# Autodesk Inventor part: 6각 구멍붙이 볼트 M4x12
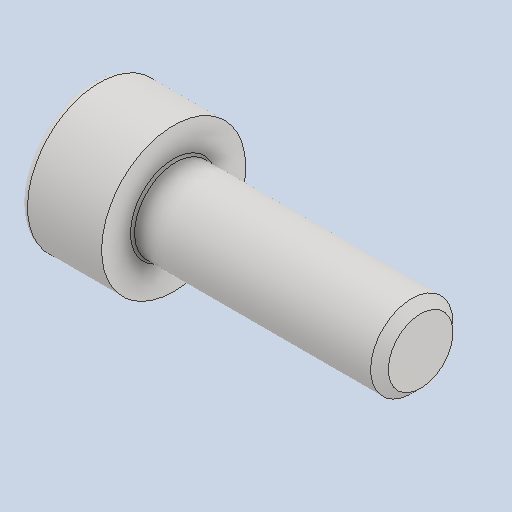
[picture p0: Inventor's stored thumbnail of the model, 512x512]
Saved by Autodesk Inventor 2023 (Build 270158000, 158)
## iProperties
Created: 2025-03
Part Number: 6각 구멍붙이 볼트 M4x12
Material: 스테인리스강
Description: 6각 소켓 머리 캡 나사
Document SubType Name: Modeling
Designer: user
Density: 8.08 g/cm^3
Appearance: 기본값
Author: jhkim
Sending System: Autodesk Inventor 2025
Preprocessor: ST-DEVELOPER v20
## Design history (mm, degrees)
feature "Solid1"
node "솔리드1"
